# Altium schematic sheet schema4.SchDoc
size A3; ApprovedBy: CdB; CheckedBy: CdB; DrawnBy: RT; Engineer: CdB; Organization: Faber Electronics B.V.; Address1: Th. Dobbeweg 1,; Address2: 6883 GN Velp,; Address3: Netherlands; Address4: T: 026-38 46 800; DocumentNumber: 4; Revision: 2.1.4; SheetNumber: 4; SheetTotal: 6; Status: Final; PageSetup: Record=PageOptions|CenterHorizontal=True|CenterVertical=True|PrintScale=1.01|XCorrection=1.00|YCorrection=1.00|PrintKind=1|BorderSize=5000000|LeftOffset=0|BottomOffset=0|Orientation=2|PaperLength=1000|PaperWidth=1000|Scale=100|PaperSource=7|PrintQuality=1200|MediaType=1|DitherType=10|PaperKind=A3 (297 x 420mm)|PrintScaleMode=1
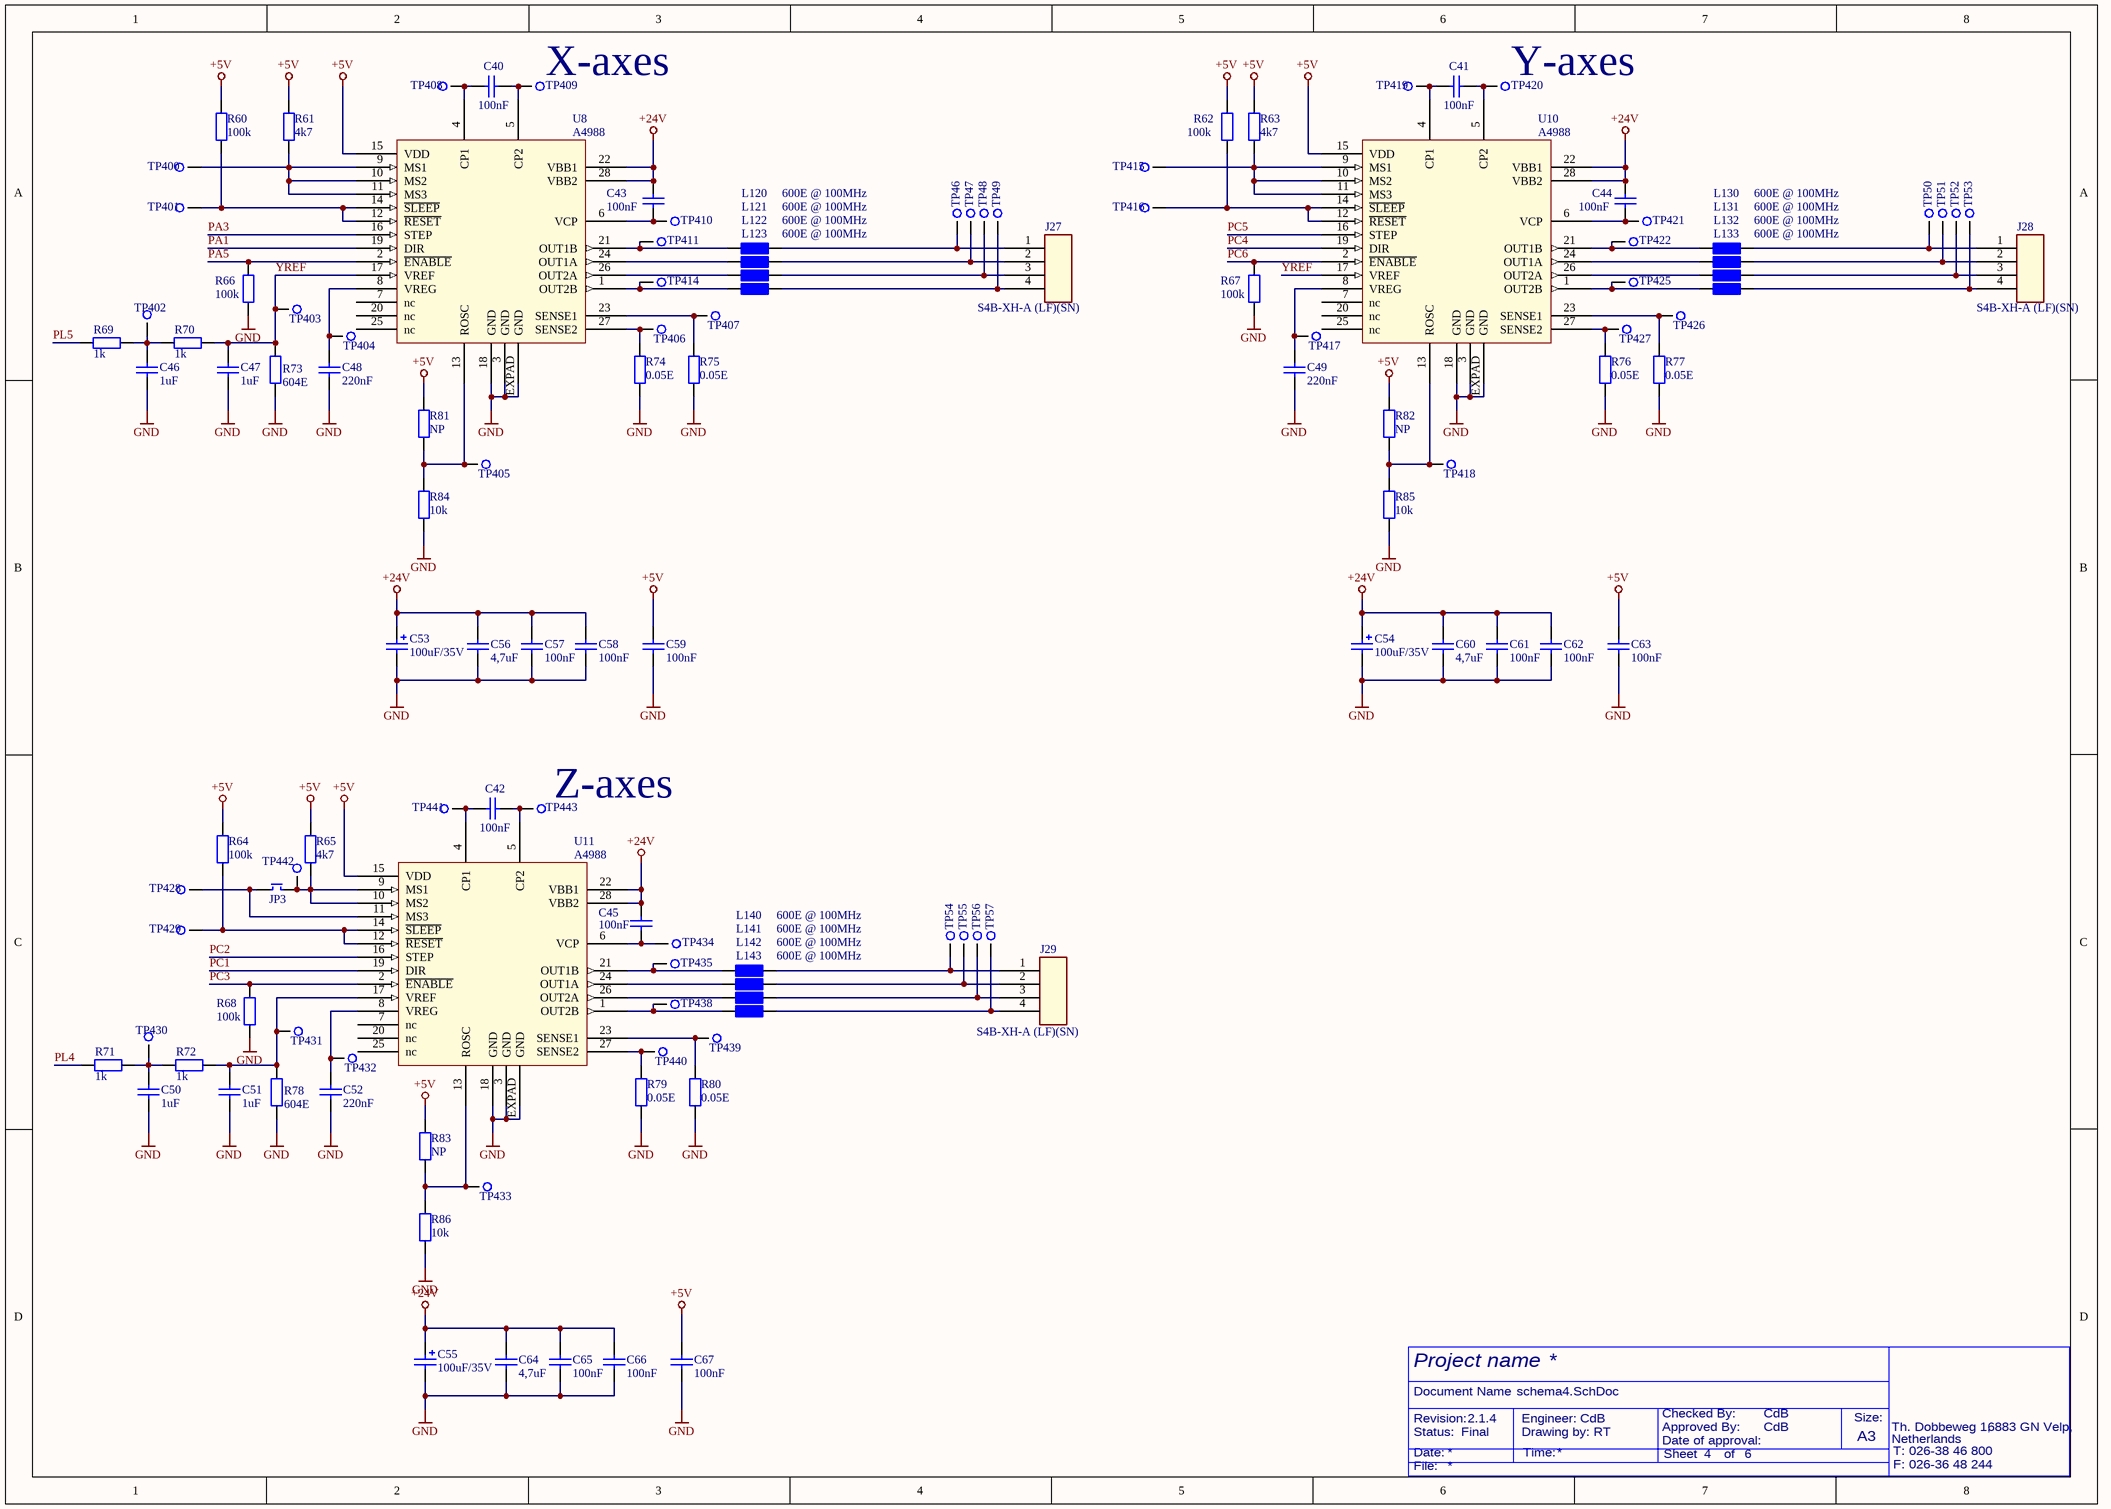
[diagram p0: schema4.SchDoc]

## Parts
C40  100nF  [C0603]
C41  100nF  [C0603]
C42  100nF  [C0603]
C43  100nF  [C0603]
C44  100nF  [C0603]
C45  100nF  [C0603]
C46  1uF  [C0603]
C47  1uF  [C0603]
C48  220nF  [C0603]
C49  220nF  [C0603]
C50  1uF  [C0603]
C51  1uF  [C0603]
C52  220nF  [C0603]
C53  100uF/35V  [ELCO Case D]
C54  100uF/35V  [ELCO Case D]
C55  100uF/35V  [ELCO Case D]
C56  4,7uF  [C1206]
C57  100nF  [C0603]
C58  100nF  [C0603]
C59  100nF  [C0603]
C60  4,7uF  [C1206]
C61  100nF  [C0603]
C62  100nF  [C0603]
C63  100nF  [C0603]
C64  4,7uF  [C1206]
C65  100nF  [C0603]
C66  100nF  [C0603]
C67  100nF  [C0603]
J27  S4B-XH-A (LF)(SN)  [S4B-XH-A (LF)(SN)]
J28  S4B-XH-A (LF)(SN)  [S4B-XH-A (LF)(SN)]
J29  S4B-XH-A (LF)(SN)  [S4B-XH-A (LF)(SN)]
JP3  HEADER 2  [HEADER-1x2P-ST-2.54]  (value not drawn)
L120  600E @ 100MHz  [R1206]
L121  600E @ 100MHz  [R1206]
L122  600E @ 100MHz  [R1206]
L123  600E @ 100MHz  [R1206]
L130  600E @ 100MHz  [R1206]
L131  600E @ 100MHz  [R1206]
L132  600E @ 100MHz  [R1206]
L133  600E @ 100MHz  [R1206]
L140  600E @ 100MHz  [R1206]
L141  600E @ 100MHz  [R1206]
L142  600E @ 100MHz  [R1206]
L143  600E @ 100MHz  [R1206]
R60  100k  [R0603]
R61  4k7  [R0603]
R62  100k  [R0603]
R63  4k7  [R0603]
R64  100k  [R0603]
R65  4k7  [R0603]
R66  100k  [R0603]
R67  100k  [R0603]
R68  100k  [R0603]
R69  1k  [R0603]
R70  1k  [R0603]
R71  1k  [R0603]
R72  1k  [R0603]
R73  604E  [R0603]
R74  0.05E  [R0805]
R75  0.05E  [R0805]
R76  0.05E  [R0805]
R77  0.05E  [R0805]
R78  604E  [R0603]
R79  0.05E  [R0805]
R80  0.05E  [R0805]
R81  NP  [R0603]
R82  NP  [R0603]
R83  NP  [R0603]
R84  10k  [R0603]
R85  10k  [R0603]
R86  10k  [R0603]
TP46  Testpoint  [Testpoint]  (value not drawn)
TP47  Testpoint  [Testpoint]  (value not drawn)
TP48  Testpoint  [Testpoint]  (value not drawn)
TP49  Testpoint  [Testpoint]  (value not drawn)
TP50  Testpoint  [Testpoint]  (value not drawn)
TP51  Testpoint  [Testpoint]  (value not drawn)
TP52  Testpoint  [Testpoint]  (value not drawn)
TP53  Testpoint  [Testpoint]  (value not drawn)
TP54  Testpoint  [Testpoint]  (value not drawn)
TP55  Testpoint  [Testpoint]  (value not drawn)
TP56  Testpoint  [Testpoint]  (value not drawn)
TP57  Testpoint  [Testpoint]  (value not drawn)
TP400  Testpoint 1mm  [Testpoint 1mm]  (value not drawn)
TP401  Testpoint 1mm  [Testpoint 1mm]  (value not drawn)
TP402  Testpoint 1mm  [Testpoint 1mm]  (value not drawn)
TP403  Testpoint 1mm  [Testpoint 1mm]  (value not drawn)
TP404  Testpoint 1mm  [Testpoint 1mm]  (value not drawn)
TP405  Testpoint 1mm  [Testpoint 1mm]  (value not drawn)
TP406  Testpoint 1mm  [Testpoint 1mm]  (value not drawn)
TP407  Testpoint 1mm  [Testpoint 1mm]  (value not drawn)
TP408  Testpoint 1mm  [Testpoint 1mm]  (value not drawn)
TP409  Testpoint 1mm  [Testpoint 1mm]  (value not drawn)
TP410  Testpoint 1mm  [Testpoint 1mm]  (value not drawn)
TP411  Testpoint 1mm  [Testpoint 1mm]  (value not drawn)
TP414  Testpoint 1mm  [Testpoint 1mm]  (value not drawn)
TP415  Testpoint 1mm  [Testpoint 1mm]  (value not drawn)
TP416  Testpoint 1mm  [Testpoint 1mm]  (value not drawn)
TP417  Testpoint 1mm  [Testpoint 1mm]  (value not drawn)
TP418  Testpoint 1mm  [Testpoint 1mm]  (value not drawn)
TP419  Testpoint 1mm  [Testpoint 1mm]  (value not drawn)
TP420  Testpoint 1mm  [Testpoint 1mm]  (value not drawn)
TP421  Testpoint 1mm  [Testpoint 1mm]  (value not drawn)
TP422  Testpoint 1mm  [Testpoint 1mm]  (value not drawn)
TP425  Testpoint 1mm  [Testpoint 1mm]  (value not drawn)
TP426  Testpoint 1mm  [Testpoint 1mm]  (value not drawn)
TP427  Testpoint 1mm  [Testpoint 1mm]  (value not drawn)
TP428  Testpoint 1mm  [Testpoint 1mm]  (value not drawn)
TP429  Testpoint 1mm  [Testpoint 1mm]  (value not drawn)
TP430  Testpoint 1mm  [Testpoint 1mm]  (value not drawn)
TP431  Testpoint 1mm  [Testpoint 1mm]  (value not drawn)
TP432  Testpoint 1mm  [Testpoint 1mm]  (value not drawn)
TP433  Testpoint 1mm  [Testpoint 1mm]  (value not drawn)
TP434  Testpoint 1mm  [Testpoint 1mm]  (value not drawn)
TP435  Testpoint 1mm  [Testpoint 1mm]  (value not drawn)
TP438  Testpoint 1mm  [Testpoint 1mm]  (value not drawn)
TP439  Testpoint 1mm  [Testpoint 1mm]  (value not drawn)
TP440  Testpoint 1mm  [Testpoint 1mm]  (value not drawn)
TP441  Testpoint 1mm  [Testpoint 1mm]  (value not drawn)
TP442  Testpoint 1mm  [Testpoint 1mm]  (value not drawn)
TP443  Testpoint 1mm  [Testpoint 1mm]  (value not drawn)
U8  A4988  [QFN50P500X500X100-28-EX]
U10  A4988  [QFN50P500X500X100-28-EX]
U11  A4988  [QFN50P500X500X100-28-EX]

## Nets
+5V: C59.2 C63.2 C67.2 R60.2 R61.2 R62.2 R63.2 R64.2 R65.2 R81.2 R82.2 R83.2 U8.15(VDD) U10.15(VDD) U11.15(VDD)
+24V: C43.2 C44.2 C45.2 C53.1 C54.1 C55.1 C56.2 C57.2 C58.2 C60.2 C61.2 C62.2 C64.2 C65.2 C66.2 U8.22(VBB1) U8.28(VBB2) U10.22(VBB1) U10.28(VBB2) U11.22(VBB1) U11.28(VBB2)
GND: C46.1 C47.1 C48.1 C49.1 C50.1 C51.1 C52.1 C53.2 C54.2 C55.2 C56.1 C57.1 C58.1 C59.1 C60.1 C61.1 C62.1 C63.1 C64.1 C65.1 C66.1 C67.1 R66.2 R67.2 R68.2 R73.1 R74.1 R75.1 R76.1 R77.1 R78.1 R79.1 R80.1 R84.1 R85.1 R86.1 U8.3(GND) U8.18(GND) U8.EXPAD(GND) U10.3(GND) U10.18(GND) U10.EXPAD(GND) U11.3(GND) U11.18(GND) U11.EXPAD(GND)
PA1: U8.19(DIR)
PA3: U8.16(STEP)
PA5: R66.1 U8.2(~{ENABLE})
PC1: U11.19(DIR)
PC2: U11.16(STEP)
PC3: R68.1 U11.2(~{ENABLE})
PC4: U10.19(DIR)
PC5: U10.16(STEP)
PC6: R67.1 U10.2(~{ENABLE})
PL4: R71.1
PL5: R69.1
YREF: C47.2 R70.2 R73.2 TP403.1 U8.17(VREF) U10.17(VREF)
NetC40_1: C40.1 TP408.1 U8.4(CP1)
NetC40_2: C40.2 TP409.1 U8.5(CP2)
NetC41_1: C41.1 TP419.1 U10.4(CP1)
NetC41_2: C41.2 TP420.1 U10.5(CP2)
NetC42_1: C42.1 TP441.1 U11.4(CP1)
NetC42_2: C42.2 TP443.1 U11.5(CP2)
NetC43_1: C43.1 TP410.1 U8.6(VCP)
NetC44_1: C44.1 TP421.1 U10.6(VCP)
NetC45_1: C45.1 TP434.1 U11.6(VCP)
NetC46_2: C46.2 R69.2 R70.1 TP402.1
NetC48_2: C48.2 TP404.1 U8.8(VREG)
NetC49_2: C49.2 TP417.1 U10.8(VREG)
NetC50_2: C50.2 R71.2 R72.1 TP430.1
NetC51_2: C51.2 R72.2 R78.2 TP431.1 U11.17(VREF)
NetC52_2: C52.2 TP432.1 U11.8(VREG)
NetJ27_1: J27.1 L120.2 TP46.1
NetJ27_2: J27.2 L121.2 TP47.1
NetJ27_3: J27.3 L122.2 TP48.1
NetJ27_4: J27.4 L123.2 TP49.1
NetJ28_1: J28.1 L130.2 TP50.1
NetJ28_2: J28.2 L131.2 TP51.1
NetJ28_3: J28.3 L132.2 TP52.1
NetJ28_4: J28.4 L133.2 TP53.1
NetJ29_1: J29.1 L140.2 TP54.1
NetJ29_2: J29.2 L141.2 TP55.1
NetJ29_3: J29.3 L142.2 TP56.1
NetJ29_4: J29.4 L143.2 TP57.1
NetJP3_1: JP3.1 TP428.1 U11.11(MS3)
NetJP3_2: JP3.2 R65.1 TP442.1 U11.9(MS1) U11.10(MS2)
NetL120_1: L120.1 TP411.1 U8.21(OUT1B)
NetL121_1: L121.1 U8.24(OUT1A)
NetL122_1: L122.1 U8.26(OUT2A)
NetL123_1: L123.1 TP414.1 U8.1(OUT2B)
NetL130_1: L130.1 TP422.1 U10.21(OUT1B)
NetL131_1: L131.1 U10.24(OUT1A)
NetL132_1: L132.1 U10.26(OUT2A)
NetL133_1: L133.1 TP425.1 U10.1(OUT2B)
NetL140_1: L140.1 TP435.1 U11.21(OUT1B)
NetL141_1: L141.1 U11.24(OUT1A)
NetL142_1: L142.1 U11.26(OUT2A)
NetL143_1: L143.1 TP438.1 U11.1(OUT2B)
NetR60_1: R60.1 TP401.1 U8.12(~{RESET}) U8.14(~{SLEEP})
NetR61_1: R61.1 TP400.1 U8.9(MS1) U8.10(MS2) U8.11(MS3)
NetR62_1: R62.1 TP416.1 U10.12(~{RESET}) U10.14(~{SLEEP})
NetR63_1: R63.1 TP415.1 U10.9(MS1) U10.10(MS2) U10.11(MS3)
NetR64_1: R64.1 TP429.1 U11.12(~{RESET}) U11.14(~{SLEEP})
NetR74_2: R74.2 TP406.1 U8.27(SENSE2)
NetR75_2: R75.2 TP407.1 U8.23(SENSE1)
NetR76_2: R76.2 TP427.1 U10.27(SENSE2)
NetR77_2: R77.2 TP426.1 U10.23(SENSE1)
NetR79_2: R79.2 TP440.1 U11.27(SENSE2)
NetR80_2: R80.2 TP439.1 U11.23(SENSE1)
NetR81_1: R81.1 R84.2 TP405.1 U8.13(ROSC)
NetR82_1: R82.1 R85.2 TP418.1 U10.13(ROSC)
NetR83_1: R83.1 R86.2 TP433.1 U11.13(ROSC)

Not connected (* = marked no-connect by the designer): U8 7(nc) 20(nc) 25(nc); U10 7(nc) 20(nc) 25(nc); U11 7(nc) 20(nc) 25(nc)

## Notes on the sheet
- (near TP409) X-axes
- (near TP420) Y-axes
- (near TP443) Z-axes

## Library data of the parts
C40-C45 C57-C59 C61-C63 C65-C67 = Library_CAP-0002: RO X7R 100nF 10% 50V 0603; Faber ItemCode: 45068500
C46 C47 C50 C51 = Library_CAP-0006: RO X5R 1uF 10% 10V 0603; Faber ItemCode: 36310600
C48 C49 C52 = Library_CAP-0001: RO X7R 220nF 10% 25V  0603; Faber ItemCode: 36126300
C53-C55 = Library_CAP-0004: RO ELCO 100uF 20% 35V CASE-D EEEFP PAN; Faber ItemCode: 36865800
C56 C60 C64 = Library_CAP-0003: RO X7R 4,7uF 10% 50V 1206; Faber ItemCode: 35404600
J27-J29 = Library_CON-0005: RO CONN PR 4p HKS S4B-XH-A (LF)(SN) JST; Mfg: JST (JAPAN SOLDERLESS TERMINALS); Faber ItemCode: 36926500
JP3 = Library_CON-0018: HEADER-1x2P-ST-2.54
L120-L123 L130-L133 L140-L143 = Ferriet Bead 600E: FERRIET 742792118 1206 Wurth Elektronik; Mfg: Wurth Elektronics; Mfg code: 1800374
R60 R62 R64 R66-R68 = Library_RES-0005: RO RES 100k0 1% 0,063W  0603; Faber ItemCode: 36257800
R61 R63 R65 = Library_RES-0002: RO RES 4k70 1% 0,063W  0603; Faber ItemCode: 36257400
R69-R72 = Library_RES-0004: RO RES 1k0 1% 0,1W  0603; Faber ItemCode: 34637900
R73 R78 = Library_RES-0018: RO RES 604E 1% 0,063W 0603; Mfg: VISHAY DRALORIC; Mfg code: CRCW0603604RFKEA; Faber ItemCode: 36932600
R74-R77 R79 R80 = Library_RES-0013: RO RES 0E05 1% 0,125W 0805; Mfg: BOURNS; Mfg code: CRL0805-FW-R050ELF; Faber ItemCode: 36925700
R81-R83 = Library_RES-0001
R84-R86 = Library_RES-0001: RO RES 10k0 1% 0,063W  0603; Faber ItemCode: 36084500
TP46-TP57 = Library_MISC-0001: Info: Testpoint, 2mm, round
TP400-TP411 TP414-TP422 TP425-TP435 TP438-TP443 = Testpoint 1mm: ID: Library_MISC-0001
U8 U10 U11 = Library_ICS-0002: RO IC A4988 QFN-28 ALLEGRO; Mfg code: A4988SETTR-T; Info: DMOS Microstepping Driver with Translator and Overcurrent Protection; Faber ItemCode: 36921600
